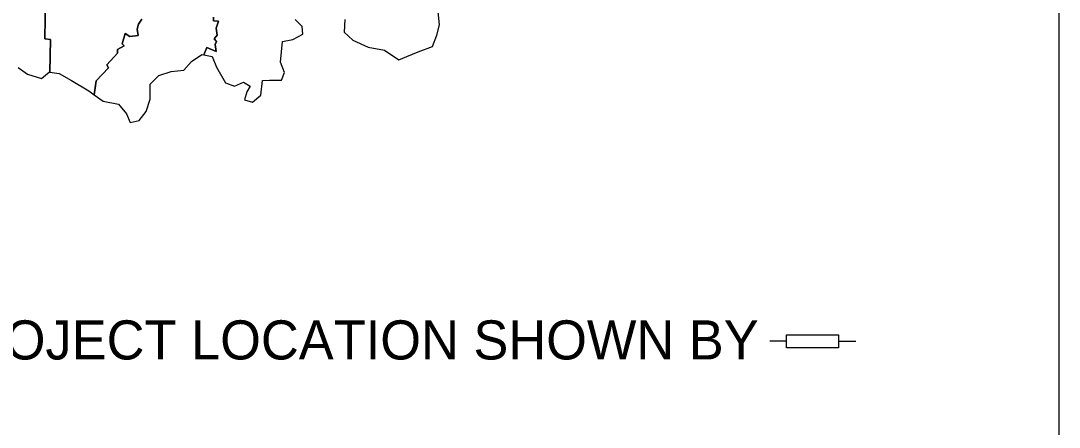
# Model space of a CAD drawing. Extents: x 0.02 to 1.09, y -0.09 to 0.68.
# Drawn here: x 0.1011 to 0.2601, y 0.3512 to 0.4135 of the extents above; entities that cross this region are included whole.
import ezdxf

# ---------------------------------------------------------------- set-up
doc = ezdxf.new("R2010")
doc.units = 0
doc.layers.add('BD_SHT', color=7, linetype='Continuous')
doc.layers.add('BD_SHT_Text', color=7, linetype='Continuous')

msp = doc.modelspace()

# ---------------------------------------------------------------- linework, layer by layer
at = {"layer": 'BD_SHT'}
for p, q in [((0.10475, 0.41074), (0.10484, 0.41719)), ((0.10484, 0.41719), (0.10475, 0.41074)), ((0.11909, 0.41298), (0.11958, 0.41374)), ((0.11958, 0.41374), (0.11909, 0.41298)), ((0.13055, 0.41347), (0.13054, 0.41403)), ((0.13054, 0.41403), (0.13055, 0.41347)), ((0.14412, 0.41263), (0.14309, 0.4137)), ((0.15069, 0.4137), (0.15059, 0.41173)), ((0.16518, 0.41288), (0.16497, 0.41485)), ((0.11886, 0.41222), (0.11909, 0.41298)), ((0.11909, 0.41298), (0.11886, 0.41222)), ((0.11901, 0.41124), (0.11886, 0.41222)), ((0.11886, 0.41222), (0.11901, 0.41124)), ((0.13131, 0.41344), (0.13055, 0.41347)), ((0.13055, 0.41347), (0.13131, 0.41344)), ((0.13098, 0.41236), (0.13131, 0.41344)), ((0.13131, 0.41344), (0.13098, 0.41236)), ((0.13111, 0.41127), (0.13098, 0.41236)), ((0.13098, 0.41236), (0.13111, 0.41127)), ((0.14423, 0.41143), (0.14412, 0.41263)), ((0.16479, 0.41128), (0.16518, 0.41288)), ((0.10561, 0.41064), (0.10475, 0.41074)), ((0.10475, 0.41074), (0.10561, 0.41064)), ((0.10552, 0.40563), (0.10561, 0.41064)), ((0.10561, 0.41064), (0.10552, 0.40563)), ((0.11659, 0.40996), (0.11703, 0.41156)), ((0.11703, 0.41156), (0.11659, 0.40996)), ((0.11703, 0.41156), (0.11773, 0.4111)), ((0.11773, 0.4111), (0.11703, 0.41156)), ((0.11773, 0.4111), (0.11901, 0.41124)), ((0.11901, 0.41124), (0.11773, 0.4111)), ((0.13066, 0.41074), (0.13111, 0.41127)), ((0.13111, 0.41127), (0.13066, 0.41074)), ((0.131, 0.41031), (0.13066, 0.41074)), ((0.13066, 0.41074), (0.131, 0.41031)), ((0.13081, 0.40987), (0.131, 0.41031)), ((0.131, 0.41031), (0.13081, 0.40987)), ((0.14085, 0.40713), (0.14113, 0.41032)), ((0.14113, 0.41032), (0.14271, 0.41061)), ((0.14271, 0.41061), (0.14423, 0.41143)), ((0.15059, 0.41173), (0.15188, 0.4105)), ((0.15188, 0.4105), (0.15423, 0.40943)), ((0.16408, 0.40953), (0.16479, 0.41128)), ((0.11585, 0.40854), (0.11586, 0.40909)), ((0.11586, 0.40909), (0.11585, 0.40854)), ((0.11586, 0.40909), (0.11689, 0.40963)), ((0.11689, 0.40963), (0.11586, 0.40909)), ((0.11689, 0.40963), (0.11659, 0.40996)), ((0.11659, 0.40996), (0.11689, 0.40963)), ((0.12908, 0.40828), (0.12954, 0.40939)), ((0.12954, 0.40939), (0.12908, 0.40828)), ((0.12954, 0.40939), (0.13096, 0.40876)), ((0.13096, 0.40876), (0.12954, 0.40939)), ((0.13096, 0.40876), (0.13081, 0.40987)), ((0.13081, 0.40987), (0.13096, 0.40876)), ((0.15423, 0.40943), (0.15674, 0.40898)), ((0.15674, 0.40898), (0.15893, 0.40749)), ((0.16018, 0.40803), (0.16191, 0.40872)), ((0.16191, 0.40872), (0.16408, 0.40953)), ((0.11423, 0.40673), (0.11585, 0.40854)), ((0.11585, 0.40854), (0.11423, 0.40673)), ((0.12604, 0.40594), (0.12719, 0.40727)), ((0.12719, 0.40727), (0.12877, 0.40834)), ((0.12877, 0.40834), (0.12908, 0.40828)), ((0.12908, 0.40828), (0.13035, 0.40801)), ((0.13035, 0.40801), (0.13105, 0.40637)), ((0.14144, 0.40557), (0.14085, 0.40713)), ((0.15893, 0.40749), (0.16018, 0.40803)), ((0.10065, 0.40634), (0.10208, 0.40533)), ((0.10422, 0.40462), (0.10545, 0.40565)), ((0.10545, 0.40565), (0.10552, 0.40563)), ((0.10552, 0.40563), (0.10695, 0.4054)), ((0.11258, 0.40427), (0.11447, 0.4063)), ((0.11447, 0.4063), (0.11258, 0.40427)), ((0.11447, 0.4063), (0.11423, 0.40673)), ((0.11423, 0.40673), (0.11447, 0.4063)), ((0.12217, 0.40509), (0.12407, 0.40572)), ((0.12407, 0.40572), (0.12604, 0.40594)), ((0.13105, 0.40637), (0.13239, 0.40396)), ((0.141, 0.40438), (0.14144, 0.40557)), ((0.10208, 0.40533), (0.10422, 0.40462)), ((0.10695, 0.4054), (0.10881, 0.40436)), ((0.10881, 0.40436), (0.11146, 0.40274)), ((0.11231, 0.40213), (0.11258, 0.40427)), ((0.11258, 0.40427), (0.11231, 0.40213)), ((0.12086, 0.40377), (0.12217, 0.40509)), ((0.13239, 0.40396), (0.13379, 0.40345)), ((0.13379, 0.40345), (0.13518, 0.4041)), ((0.13518, 0.4041), (0.13616, 0.40346)), ((0.13779, 0.40209), (0.13809, 0.40433)), ((0.13809, 0.40433), (0.13916, 0.40441)), ((0.13916, 0.40441), (0.141, 0.40438)), ((0.11146, 0.40274), (0.11231, 0.40213)), ((0.12085, 0.40146), (0.12086, 0.40377)), ((0.13569, 0.40261), (0.13531, 0.40139)), ((0.13616, 0.40346), (0.13569, 0.40261)), ((0.11231, 0.40213), (0.11367, 0.40115)), ((0.11367, 0.40115), (0.11603, 0.40073)), ((0.12025, 0.39956), (0.12085, 0.40146)), ((0.13531, 0.40139), (0.13655, 0.401)), ((0.13655, 0.401), (0.13779, 0.40209)), ((0.11603, 0.40073), (0.11722, 0.39924)), ((0.11722, 0.39924), (0.11778, 0.39792)), ((0.11917, 0.3982), (0.12025, 0.39956)), ((0.11778, 0.39792), (0.11917, 0.3982)), ((0.21829, 0.36435), (0.21577, 0.36435)), ((0.22628, 0.36435), (0.22892, 0.36435))]:
    msp.add_line(p, q, dxfattribs=at)
msp.add_lwpolyline([(0.03924, 0.33397), (0.26008, 0.33397), (0.26008, 0.65078), (0.03924, 0.65078), (0.03924, 0.33397)], dxfattribs=at)
msp.add_lwpolyline([(0.21829, 0.36535), (0.22628, 0.36535), (0.22628, 0.36336), (0.21829, 0.36336)], close=True, dxfattribs=at)

# ---------------------------------------------------------------- texts
at = {"layer": 'BD_SHT_Text'}
msp.add_text('PROJECT LOCATION SHOWN BY', height=0.006, dxfattribs=at).set_placement((0.08745, 0.36155))

doc.saveas('drawing.dxf')
